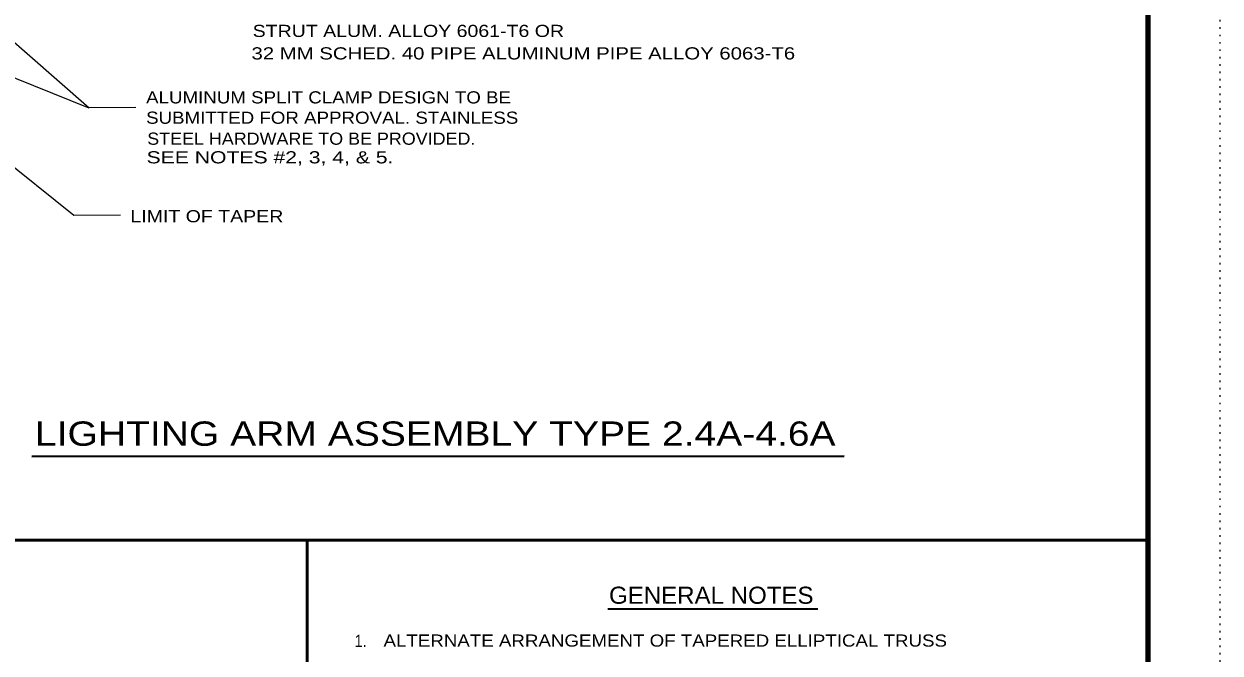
# Model space of a CAD drawing. Extents: x 312583 to 312854, y 144419 to 144597.
# Drawn here: x 312778.8 to 312853.5, y 144506.5 to 144545.9 of the extents above; entities that cross this region are included whole.
import ezdxf
from ezdxf.enums import TextEntityAlignment as Align

# ---------------------------------------------------------------- set-up
doc = ezdxf.new("R2010")
doc.units = 0
doc.header["$LTSCALE"] = 0.3
doc.linetypes.add('DOTTED', pattern=[1.5, 0.3, -1.2])
for name, color, linetype, lineweight in [('1', 7, 'Continuous', 35), ('2', 7, 'Continuous', 13), ('62', 7, 'DOTTED', 13)]:
    doc.layers.add(name, color=color, linetype=linetype, lineweight=lineweight)

msp = doc.modelspace()

# ---------------------------------------------------------------- linework, layer by layer
at = {"layer": '1', "lineweight": 158}
msp.add_line((312849, 144423.1446), (312849, 144585.0846), dxfattribs=at)
at = {"layer": '1', "lineweight": 53}
for p, q in [((312849, 144513.591), (312723.535, 144513.591)), ((312796.4617, 144513.591), (312796.4617, 144460.0203))]:
    msp.add_line(p, q, dxfattribs=at)
at = {"layer": '1'}
msp.add_line((312828.3633, 144509.2841), (312815.2527, 144509.2841), dxfattribs=at)
at = {"layer": '2'}
for p, q in [((312782.8444, 144540.598), (312770.4857, 144551.4233)), ((312782.8444, 144540.598), (312770.616, 144545.5123)), ((312781.8937, 144533.8743), (312769.5274, 144543.8103)), ((312785.7577, 144540.6363), (312782.8367, 144540.6056)), ((312784.8147, 144533.8973), (312781.8937, 144533.882))]:
    msp.add_line(p, q, dxfattribs=at)
at = {"layer": '2', "lineweight": 40}
msp.add_line((312830.0222, 144518.8341), (312779.271, 144518.8147), dxfattribs=at)
at = {"layer": '62'}
msp.add_lwpolyline([(312601.2, 144418.5846), (312853.5, 144418.5846), (312853.5, 144596.7846)], dxfattribs=at)

# ---------------------------------------------------------------- texts
at = {"layer": '1', "width": 0.9}
msp.add_text('1.', height=0.76, dxfattribs=at).set_placement((312799.428, 144506.9181))
at = {"layer": '2'}
for s, width, p in [('STRUT ALUM. ALLOY 6061-T6 OR', 1.2, (312793.0662, 144545.0399)), ('32 MM SCHED. 40 PIPE ALUMINUM PIPE ALLOY 6063-T6', 1.25, (312792.9937, 144543.636)), ('ALUMINUM SPLIT CLAMP DESIGN TO BE', 1.15, (312786.4098, 144540.8864)), ('SUBMITTED FOR APPROVAL. STAINLESS', 1.15, (312786.4087, 144539.6147)), ('STEEL HARDWARE TO BE PROVIDED.', 1.1, (312786.4807, 144538.3056)), ('SEE NOTES #2, 3, 4, & 5.', 1.3, (312786.4383, 144537.1404)), ('LIMIT OF TAPER', 1.2, (312785.428, 144533.4584)), ('ALTERNATE ARRANGEMENT OF TAPERED ELLIPTICAL TRUSS   ', 1.15, (312801.241, 144506.9371))]:
    msp.add_text(s, height=0.76, dxfattribs=dict(at, width=width)).set_placement(p)
for s, height, width, p in [('LIGHTING ARM ASSEMBLY TYPE 2.4A-4.6A', 1.52, 1.2, (312804.4728, 144519.4917)), ('GENERAL NOTES', 1.07, 1.05, (312821.715, 144509.6162))]:
    msp.add_text(s, height=height, dxfattribs=dict(at, width=width)).set_placement(p, align=Align.CENTER)

doc.saveas('drawing.dxf')
